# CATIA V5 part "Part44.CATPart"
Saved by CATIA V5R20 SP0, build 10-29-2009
Part number: FA 042200-2
Revision: ANY
Definition: UNKNOWN
Nomenclature: FA 042200-2
Source: Unknown
Bounding box of the stored display mesh (mm): x -1.5 to 1.5, y 0 to 3.7, z -1.5 to 1.5
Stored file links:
  C:\Users\Utente\Desktop\IO LAVORO\3D X SITO CF\CUMSA\3D files FA\FA 042200\Part44.CATPart

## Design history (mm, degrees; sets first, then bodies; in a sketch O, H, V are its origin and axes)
Body1 "Cortar-Extruir1" (main body)
  Solid1: solid without history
